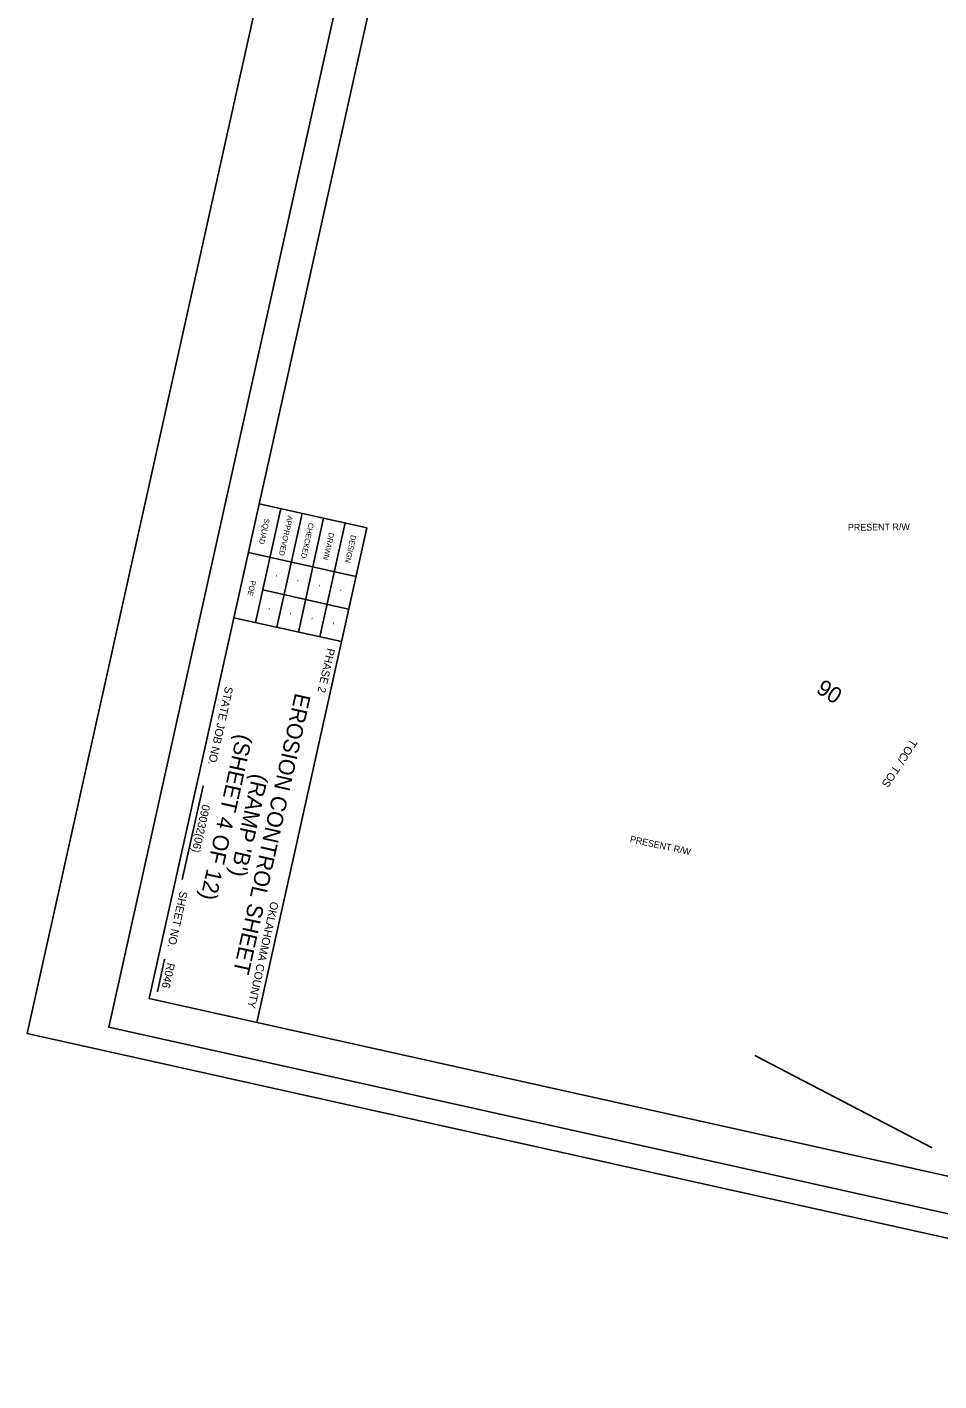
# Model space of a CAD drawing. Extents: x 2149822 to 2151384, y 143435 to 145586.
# Drawn here: x 2149822 to 2150506, y 143568 to 144584 of the extents above; entities that cross this region are included whole.
import ezdxf

# ---------------------------------------------------------------- set-up
doc = ezdxf.new("R2010")
doc.units = 0
for name, color, linetype in [('ALIGN_ROW Text', 7, 'Continuous'), ('PR_Align_Ramp_B', 7, 'Continuous'), ('PR_Align_Service_C_Sta', 7, 'Continuous'), ('PR_Grading_Txt', 7, 'Continuous'), ('SHT_Plot_Shape_Full', 7, 'Continuous'), ('SHT_Plot_Shape_Half', 7, 'Continuous'), ('SHT_Sheet_Border', 7, 'Continuous'), ('SHT_Standard_Sheet_Lines', 7, 'Continuous'), ('SHT_Standard_Sheet_Txt', 7, 'Continuous')]:
    doc.layers.add(name, color=color, linetype=linetype)

msp = doc.modelspace()

# ---------------------------------------------------------------- linework, layer by layer
at = {"layer": 'PR_Align_Ramp_B'}
msp.add_line((2150500.8, 143743.3), (2150367.8, 143812.5), dxfattribs=at)
at = {"layer": 'SHT_Plot_Shape_Full'}
msp.add_lwpolyline([(2151384.1, 145325.5), (2150993.4, 143568.4), (2149822, 143828.9), (2150212.7, 145586)], close=True, dxfattribs=at)
at = {"layer": 'SHT_Plot_Shape_Half'}
msp.add_lwpolyline([(2151326, 145254.5), (2150957, 143595.1), (2149883.3, 143833.8), (2150252.3, 145493.3)], close=True, dxfattribs=at)
at = {"layer": 'SHT_Sheet_Border'}
for p, q in [((2149996.1, 144226.2), (2150076.7, 144208.3)), ((2150076.7, 144208.3), (2149994.2, 143837.3)), ((2149977.1, 144140.8), (2150057.7, 144122.9))]:
    msp.add_line(p, q, dxfattribs=at)
msp.add_lwpolyline([(2149913.6, 143855.3), (2150255.5, 145392.7), (2151280.5, 145164.8), (2150938.6, 143627.3)], close=True, dxfattribs=at)
at = {"layer": 'SHT_Standard_Sheet_Lines'}
for p, q in [((2149988, 144189.6), (2150068.6, 144171.7)), ((2149998.7, 144161.6), (2150063.1, 144147.3)), ((2149954, 144014.8), (2149938.4, 143944.5)), ((2149925.1, 143884.7), (2149919.7, 143860.2))]:
    msp.add_line(p, q, dxfattribs=at)
for points in [[(2149993.2, 144137.2), (2150012.2, 144222.6)], [(2150009.3, 144133.6), (2150028.3, 144219)], [(2150025.5, 144130), (2150044.4, 144215.4)], [(2150041.6, 144126.5), (2150060.6, 144211.9)]]:
    msp.add_lwpolyline(points, dxfattribs=at)

# ---------------------------------------------------------------- texts
at = {"layer": 'ALIGN_ROW Text'}
for rotation, p in [(0.5896, (2150437.6, 144206)), (347.6996, (2150273.8, 143972.5))]:
    msp.add_text('PRESENT R/W', height=5, rotation=rotation, dxfattribs=at).set_placement(p)
at = {"layer": 'PR_Align_Service_C_Sta'}
msp.add_text('90', height=12, rotation=327.5808, dxfattribs=at).set_placement((2150413, 144085.1))
at = {"layer": 'PR_Grading_Txt'}
for s, rotation, p in [('O', 237.2616, (2150481.7, 144045.3)), ('T', 237.4987, (2150484.9, 144050.3)), ('/', 236.8269, (2150475.3, 144035.4)), ('C', 237.0304, (2150478.6, 144040.4)), ('S', 236.1071, (2150465.6, 144020.7)), ('O', 236.3121, (2150468.9, 144025.6)), ('T', 236.5503, (2150472.1, 144030.5))]:
    msp.add_text(s, height=6, rotation=rotation, dxfattribs=at).set_placement(p)
at = {"layer": 'SHT_Standard_Sheet_Txt'}
for s, height, p in [('SQUAD', 4, (2150000.1, 144215.5)), ('APPROVED', 4, (2150017.5, 144217.7)), ('CHECKED', 4, (2150033.2, 144212.2)), ('DRAWN', 4, (2150048.5, 144204.9)), ('DESIGN', 4, (2150065, 144203.1)), ('-', 4, (2150007.7, 144173.4)), ('POE', 4, (2149989.8, 144169)), ('-', 4, (2150023.8, 144169.8)), ('-', 4, (2150039.9, 144166.2)), ('-', 4, (2150056, 144162.7)), ('-', 4, (2150002.2, 144148.6)), ('-', 4, (2150018.3, 144145)), ('-', 4, (2150034.4, 144141.4)), ('-', 4, (2150050.5, 144137.8)), ('PHASE 2', 6, (2150047.1, 144118.3)), ('STATE JOB NO.', 6, (2149970.7, 144089.6)), ('EROSION CONTROL SHEET', 12, (2150023.1, 144084.8)), ('(SHEET 4 OF 12)', 12, (2149979.4, 144054.1)), ("(RAMP 'B')", 12, (2149991.2, 144024.4)), ('09032(06)', 6, (2149953.5, 144001.1)), ('SHEET NO. ', 6, (2149936.6, 143936.2)), ('OKLAHOMA COUNTY', 6, (2150004.8, 143928.3)), ('R046', 6, (2149927.1, 143882.4))]:
    msp.add_text(s, height=height, rotation=257.4638, dxfattribs=at).set_placement(p)

doc.saveas('drawing.dxf')
